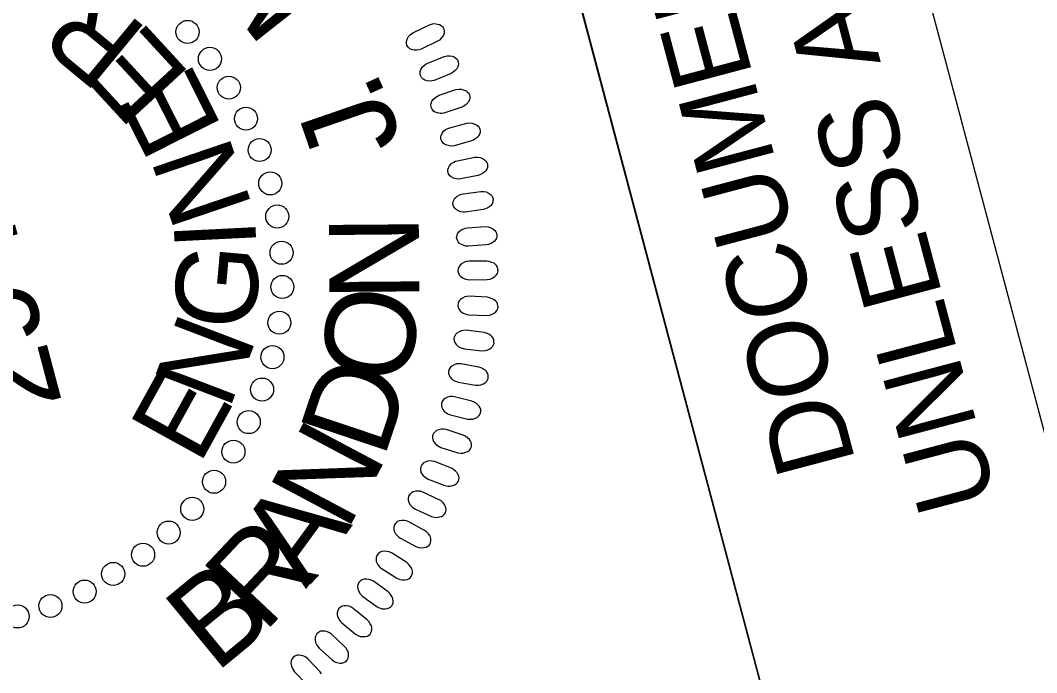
# Model space of a CAD drawing. Extents: x 473963 to 475454, y 503101 to 505009.
# Drawn here: x 474132.4 to 474202.9, y 504570.7 to 504616 of the extents above; entities that cross this region are included whole.
import ezdxf

# ---------------------------------------------------------------- set-up
doc = ezdxf.new("R2010")
doc.units = 0
for name, color, linetype in [('Old_Level_62', 7, 'Continuous'), ('Prop PHM Label Text', 7, 'Continuous'), ('Scratch_Level_4', 7, 'Continuous')]:
    doc.layers.add(name, color=color, linetype=linetype)

msp = doc.modelspace()

# ---------------------------------------------------------------- linework, layer by layer
at = {"layer": 'Old_Level_62'}
for p, q in [((474157.153, 504761.696), (474208.514, 504568.365)), ((474157.153, 504761.696), (474208.514, 504568.365)), ((474185.802, 504562.331), (474134.441, 504755.662)), ((474185.802, 504562.331), (474134.441, 504755.662))]:
    msp.add_line(p, q, dxfattribs=at)
at = {"layer": 'Prop PHM Label Text'}
msp.add_lwpolyline([(474077.089, 504533.437), (474051.4, 504630.133), (474160.141, 504659.021), (474185.802, 504562.331)], close=True, dxfattribs=at)
at = {"layer": 'Scratch_Level_4'}
for points in [[(474159.665, 504615.206), (474160.771, 504615.737), (474160.985, 504615.799), (474161.133, 504615.812), (474161.335, 504615.785), (474161.476, 504615.744), (474161.597, 504615.678), (474161.678, 504615.601), (474161.744, 504615.508), (474161.774, 504615.398), (474161.799, 504615.278), (474161.791, 504615.157), (474161.746, 504615.02), (474161.7, 504614.932), (474161.594, 504614.806), (474161.459, 504614.674), (474161.324, 504614.585), (474160.195, 504614.034), (474160.033, 504613.981), (474159.887, 504613.961), (474159.705, 504613.973), (474159.53, 504614.013), (474159.416, 504614.066), (474159.294, 504614.182), (474159.212, 504614.308), (474159.183, 504614.46), (474159.182, 504614.576), (474159.217, 504614.734), (474159.318, 504614.915), (474159.451, 504615.054), (474159.555, 504615.137)], [(474160.656, 504613.074), (474161.793, 504613.535), (474162.01, 504613.583), (474162.16, 504613.587), (474162.359, 504613.547), (474162.497, 504613.498), (474162.613, 504613.424), (474162.689, 504613.342), (474162.75, 504613.245), (474162.773, 504613.134), (474162.791, 504613.012), (474162.775, 504612.892), (474162.721, 504612.758), (474162.67, 504612.672), (474162.556, 504612.553), (474162.413, 504612.431), (474162.273, 504612.35), (474161.111, 504611.871), (474160.946, 504611.829), (474160.8, 504611.818), (474160.618, 504611.841), (474160.447, 504611.892), (474160.336, 504611.952), (474160.222, 504612.075), (474160.147, 504612.207), (474160.128, 504612.36), (474160.135, 504612.476), (474160.179, 504612.631), (474160.292, 504612.805), (474160.433, 504612.936), (474160.542, 504613.011)], [(474161.451, 504610.838), (474162.615, 504611.226), (474162.835, 504611.26), (474162.983, 504611.255), (474163.18, 504611.202), (474163.315, 504611.145), (474163.426, 504611.063), (474163.497, 504610.977), (474163.551, 504610.877), (474163.567, 504610.765), (474163.577, 504610.641), (474163.554, 504610.523), (474163.492, 504610.392), (474163.435, 504610.31), (474163.315, 504610.199), (474163.163, 504610.085), (474163.019, 504610.014), (474161.83, 504609.608), (474161.662, 504609.576), (474161.515, 504609.575), (474161.335, 504609.61), (474161.167, 504609.671), (474161.061, 504609.739), (474160.954, 504609.868), (474160.888, 504610.004), (474160.879, 504610.158), (474160.893, 504610.273), (474160.947, 504610.425), (474161.07, 504610.592), (474161.219, 504610.714), (474161.333, 504610.783)], [(474162.177, 504608.581), (474163.363, 504608.896), (474163.584, 504608.916), (474163.733, 504608.901), (474163.926, 504608.836), (474164.057, 504608.77), (474164.163, 504608.682), (474164.228, 504608.592), (474164.275, 504608.488), (474164.285, 504608.375), (474164.287, 504608.252), (474164.257, 504608.135), (474164.186, 504608.008), (474164.124, 504607.93), (474163.997, 504607.827), (474163.839, 504607.723), (474163.691, 504607.66), (474162.478, 504607.331), (474162.309, 504607.309), (474162.162, 504607.317), (474161.985, 504607.362), (474161.821, 504607.435), (474161.719, 504607.509), (474161.621, 504607.645), (474161.563, 504607.785), (474161.563, 504607.939), (474161.585, 504608.053), (474161.648, 504608.202), (474161.782, 504608.36), (474161.938, 504608.472), (474162.056, 504608.533)], [(474162.712, 504606.289), (474163.915, 504606.528), (474164.137, 504606.534), (474164.285, 504606.51), (474164.473, 504606.433), (474164.6, 504606.36), (474164.699, 504606.265), (474164.759, 504606.17), (474164.801, 504606.063), (474164.802, 504605.95), (474164.797, 504605.827), (474164.759, 504605.713), (474164.681, 504605.591), (474164.615, 504605.516), (474164.481, 504605.421), (474164.317, 504605.327), (474164.164, 504605.274), (474162.934, 504605.022), (474162.763, 504605.011), (474162.617, 504605.028), (474162.443, 504605.084), (474162.284, 504605.166), (474162.187, 504605.247), (474162.098, 504605.389), (474162.049, 504605.532), (474162.059, 504605.686), (474162.088, 504605.798), (474162.16, 504605.943), (474162.304, 504606.093), (474162.467, 504606.194), (474162.588, 504606.248)], [(474163.116, 504603.998), (474164.332, 504604.161), (474164.554, 504604.154), (474164.7, 504604.121), (474164.883, 504604.032), (474165.004, 504603.95), (474165.099, 504603.85), (474165.152, 504603.752), (474165.186, 504603.643), (474165.181, 504603.53), (474165.168, 504603.407), (474165.123, 504603.295), (474165.037, 504603.179), (474164.966, 504603.108), (474164.827, 504603.022), (474164.657, 504602.938), (474164.502, 504602.895), (474163.258, 504602.72), (474163.087, 504602.72), (474162.942, 504602.746), (474162.773, 504602.813), (474162.619, 504602.905), (474162.527, 504602.991), (474162.447, 504603.139), (474162.407, 504603.285), (474162.427, 504603.438), (474162.462, 504603.548), (474162.544, 504603.688), (474162.696, 504603.828), (474162.865, 504603.919), (474162.99, 504603.966)], [(474163.408, 504601.628), (474164.632, 504601.714), (474164.853, 504601.693), (474164.997, 504601.651), (474165.174, 504601.551), (474165.29, 504601.461), (474165.377, 504601.355), (474165.425, 504601.254), (474165.452, 504601.143), (474165.44, 504601.03), (474165.419, 504600.909), (474165.367, 504600.8), (474165.275, 504600.689), (474165.199, 504600.623), (474165.055, 504600.546), (474164.88, 504600.473), (474164.722, 504600.439), (474163.47, 504600.343), (474163.299, 504600.354), (474163.156, 504600.389), (474162.991, 504600.467), (474162.844, 504600.569), (474162.757, 504600.66), (474162.687, 504600.812), (474162.656, 504600.961), (474162.686, 504601.112), (474162.728, 504601.22), (474162.817, 504601.354), (474162.979, 504601.484), (474163.153, 504601.565), (474163.28, 504601.603)], [(474163.551, 504598.022), (474164.778, 504598.031), (474164.996, 504598.071), (474165.136, 504598.123), (474165.305, 504598.237), (474165.414, 504598.335), (474165.493, 504598.448), (474165.532, 504598.553), (474165.551, 504598.665), (474165.53, 504598.777), (474165.499, 504598.897), (474165.439, 504599.001), (474165.338, 504599.104), (474165.258, 504599.164), (474165.108, 504599.23), (474164.927, 504599.288), (474164.768, 504599.309), (474163.511, 504599.307), (474163.342, 504599.283), (474163.203, 504599.237), (474163.044, 504599.146), (474162.905, 504599.033), (474162.826, 504598.935), (474162.767, 504598.777), (474162.749, 504598.628), (474162.79, 504598.478), (474162.841, 504598.374), (474162.941, 504598.248), (474163.112, 504598.13), (474163.292, 504598.064), (474163.422, 504598.035)], [(474163.5, 504595.594), (474164.725, 504595.527), (474164.946, 504595.552), (474165.088, 504595.596), (474165.264, 504595.699), (474165.379, 504595.79), (474165.464, 504595.899), (474165.51, 504596), (474165.536, 504596.111), (474165.522, 504596.224), (474165.499, 504596.345), (474165.445, 504596.453), (474165.351, 504596.563), (474165.275, 504596.627), (474165.129, 504596.703), (474164.953, 504596.772), (474164.795, 504596.803), (474163.541, 504596.88), (474163.37, 504596.866), (474163.228, 504596.829), (474163.064, 504596.748), (474162.919, 504596.644), (474162.833, 504596.551), (474162.765, 504596.398), (474162.737, 504596.25), (474162.769, 504596.098), (474162.813, 504595.991), (474162.905, 504595.858), (474163.068, 504595.73), (474163.244, 504595.653), (474163.372, 504595.616)], [(474163.195, 504593.228), (474164.413, 504593.084), (474164.636, 504593.095), (474164.781, 504593.13), (474164.962, 504593.222), (474165.083, 504593.305), (474165.175, 504593.408), (474165.227, 504593.507), (474165.26, 504593.616), (474165.253, 504593.729), (474165.237, 504593.852), (474165.191, 504593.963), (474165.103, 504594.078), (474165.031, 504594.147), (474164.891, 504594.231), (474164.72, 504594.312), (474164.564, 504594.353), (474163.316, 504594.508), (474163.146, 504594.506), (474163.002, 504594.477), (474162.833, 504594.407), (474162.681, 504594.312), (474162.59, 504594.225), (474162.512, 504594.076), (474162.475, 504593.929), (474162.498, 504593.777), (474162.535, 504593.667), (474162.618, 504593.529), (474162.773, 504593.391), (474162.944, 504593.303), (474163.068, 504593.258)], [(474162.767, 504590.913), (474163.974, 504590.693), (474164.196, 504590.69), (474164.343, 504590.716), (474164.53, 504590.796), (474164.656, 504590.872), (474164.754, 504590.968), (474164.812, 504591.063), (474164.852, 504591.171), (474164.852, 504591.284), (474164.844, 504591.407), (474164.804, 504591.521), (474164.725, 504591.642), (474164.657, 504591.716), (474164.522, 504591.808), (474164.356, 504591.9), (474164.203, 504591.951), (474162.969, 504592.183), (474162.797, 504592.191), (474162.652, 504592.172), (474162.479, 504592.113), (474162.321, 504592.028), (474162.226, 504591.946), (474162.139, 504591.802), (474162.092, 504591.658), (474162.104, 504591.505), (474162.135, 504591.392), (474162.21, 504591.25), (474162.355, 504591.102), (474162.52, 504591.004), (474162.642, 504590.951)], [(474162.226, 504588.638), (474163.417, 504588.343), (474163.639, 504588.326), (474163.787, 504588.343), (474163.979, 504588.411), (474164.109, 504588.479), (474164.213, 504588.569), (474164.277, 504588.66), (474164.323, 504588.765), (474164.331, 504588.878), (474164.331, 504589.001), (474164.298, 504589.117), (474164.226, 504589.243), (474164.164, 504589.32), (474164.034, 504589.422), (474163.874, 504589.523), (474163.725, 504589.583), (474162.507, 504589.893), (474162.338, 504589.912), (474162.191, 504589.902), (474162.015, 504589.854), (474161.852, 504589.779), (474161.751, 504589.703), (474161.655, 504589.565), (474161.6, 504589.425), (474161.603, 504589.271), (474161.626, 504589.157), (474161.692, 504589.009), (474161.828, 504588.853), (474161.986, 504588.744), (474162.104, 504588.684)], [(474161.57, 504586.376), (474162.74, 504586.006), (474162.96, 504585.976), (474163.109, 504585.983), (474163.305, 504586.039), (474163.438, 504586.099), (474163.548, 504586.182), (474163.618, 504586.269), (474163.67, 504586.37), (474163.685, 504586.483), (474163.693, 504586.606), (474163.667, 504586.724), (474163.604, 504586.854), (474163.546, 504586.935), (474163.424, 504587.044), (474163.271, 504587.155), (474163.125, 504587.225), (474161.929, 504587.611), (474161.76, 504587.64), (474161.614, 504587.639), (474161.435, 504587.602), (474161.268, 504587.538), (474161.162, 504587.468), (474161.057, 504587.337), (474160.994, 504587.2), (474160.987, 504587.046), (474161.003, 504586.931), (474161.059, 504586.78), (474161.185, 504586.615), (474161.337, 504586.496), (474161.451, 504586.429)], [(474160.692, 504584.175), (474161.837, 504583.733), (474162.055, 504583.689), (474162.204, 504583.687), (474162.403, 504583.73), (474162.54, 504583.782), (474162.655, 504583.857), (474162.73, 504583.94), (474162.789, 504584.038), (474162.811, 504584.149), (474162.825, 504584.272), (474162.808, 504584.391), (474162.752, 504584.525), (474162.7, 504584.609), (474162.584, 504584.726), (474162.438, 504584.846), (474162.298, 504584.925), (474161.129, 504585.385), (474160.962, 504585.425), (474160.816, 504585.433), (474160.635, 504585.408), (474160.464, 504585.354), (474160.355, 504585.292), (474160.242, 504585.167), (474160.169, 504585.034), (474160.153, 504584.88), (474160.162, 504584.765), (474160.208, 504584.611), (474160.324, 504584.438), (474160.467, 504584.31), (474160.577, 504584.236)], [(474159.796, 504582.094), (474160.91, 504581.58), (474161.125, 504581.523), (474161.274, 504581.512), (474161.475, 504581.543), (474161.615, 504581.586), (474161.735, 504581.653), (474161.815, 504581.732), (474161.88, 504581.826), (474161.908, 504581.935), (474161.931, 504582.056), (474161.921, 504582.176), (474161.873, 504582.314), (474161.827, 504582.401), (474161.719, 504582.525), (474161.581, 504582.654), (474161.445, 504582.742), (474160.307, 504583.274), (474160.144, 504583.325), (474159.998, 504583.342), (474159.816, 504583.328), (474159.642, 504583.285), (474159.528, 504583.229), (474159.409, 504583.112), (474159.328, 504582.984), (474159.302, 504582.832), (474159.304, 504582.716), (474159.341, 504582.559), (474159.445, 504582.38), (474159.58, 504582.242), (474159.685, 504582.162)], [(474158.751, 504580.068), (474159.831, 504579.486), (474160.042, 504579.414), (474160.189, 504579.394), (474160.392, 504579.412), (474160.535, 504579.446), (474160.658, 504579.506), (474160.742, 504579.579), (474160.813, 504579.669), (474160.849, 504579.777), (474160.879, 504579.897), (474160.877, 504580.017), (474160.838, 504580.156), (474160.797, 504580.247), (474160.697, 504580.378), (474160.567, 504580.515), (474160.438, 504580.611), (474159.335, 504581.214), (474159.175, 504581.274), (474159.031, 504581.301), (474158.848, 504581.298), (474158.672, 504581.266), (474158.556, 504581.218), (474158.428, 504581.109), (474158.339, 504580.986), (474158.304, 504580.835), (474158.299, 504580.72), (474158.325, 504580.561), (474158.418, 504580.375), (474158.544, 504580.23), (474158.644, 504580.142)], [(474157.478, 504577.934), (474158.519, 504577.285), (474158.724, 504577.201), (474158.871, 504577.171), (474159.074, 504577.176), (474159.219, 504577.201), (474159.346, 504577.254), (474159.435, 504577.322), (474159.511, 504577.406), (474159.553, 504577.512), (474159.591, 504577.63), (474159.596, 504577.75), (474159.566, 504577.892), (474159.531, 504577.984), (474159.439, 504578.121), (474159.319, 504578.267), (474159.195, 504578.37), (474158.133, 504579.041), (474157.977, 504579.112), (474157.835, 504579.147), (474157.652, 504579.156), (474157.474, 504579.135), (474157.355, 504579.094), (474157.221, 504578.993), (474157.125, 504578.876), (474157.08, 504578.728), (474157.067, 504578.613), (474157.084, 504578.452), (474157.165, 504578.262), (474157.282, 504578.109), (474157.376, 504578.016)], [(474156.155, 504576.02), (474157.153, 504575.307), (474157.353, 504575.21), (474157.497, 504575.171), (474157.7, 504575.164), (474157.846, 504575.179), (474157.976, 504575.224), (474158.069, 504575.286), (474158.15, 504575.366), (474158.199, 504575.468), (474158.244, 504575.583), (474158.257, 504575.703), (474158.236, 504575.846), (474158.206, 504575.941), (474158.123, 504576.083), (474158.012, 504576.236), (474157.896, 504576.347), (474156.877, 504577.084), (474156.727, 504577.164), (474156.586, 504577.208), (474156.405, 504577.228), (474156.226, 504577.218), (474156.105, 504577.186), (474155.964, 504577.093), (474155.861, 504576.982), (474155.807, 504576.838), (474155.787, 504576.723), (474155.794, 504576.562), (474155.862, 504576.366), (474155.969, 504576.207), (474156.058, 504576.107)], [(474154.696, 504574.181), (474155.648, 504573.406), (474155.842, 504573.297), (474155.983, 504573.248), (474156.185, 504573.229), (474156.332, 504573.235), (474156.464, 504573.272), (474156.561, 504573.328), (474156.648, 504573.402), (474156.703, 504573.501), (474156.755, 504573.613), (474156.775, 504573.732), (474156.763, 504573.876), (474156.739, 504573.973), (474156.666, 504574.12), (474156.565, 504574.279), (474156.455, 504574.398), (474155.485, 504575.196), (474155.339, 504575.286), (474155.203, 504575.339), (474155.022, 504575.371), (474154.844, 504575.372), (474154.72, 504575.347), (474154.574, 504575.263), (474154.465, 504575.159), (474154.402, 504575.018), (474154.374, 504574.906), (474154.371, 504574.744), (474154.427, 504574.545), (474154.524, 504574.379), (474154.605, 504574.274)], [(474153.115, 504572.44), (474154.017, 504571.607), (474154.203, 504571.485), (474154.341, 504571.429), (474154.542, 504571.397), (474154.688, 504571.393), (474154.823, 504571.422), (474154.923, 504571.472), (474155.014, 504571.54), (474155.075, 504571.637), (474155.134, 504571.744), (474155.162, 504571.862), (474155.159, 504572.006), (474155.141, 504572.104), (474155.077, 504572.256), (474154.986, 504572.421), (474154.884, 504572.546), (474153.966, 504573.404), (474153.827, 504573.503), (474153.693, 504573.564), (474153.515, 504573.607), (474153.337, 504573.62), (474153.212, 504573.602), (474153.061, 504573.527), (474152.945, 504573.431), (474152.873, 504573.295), (474152.839, 504573.184), (474152.826, 504573.022), (474152.869, 504572.82), (474152.956, 504572.648), (474153.031, 504572.539)]]:
    msp.add_lwpolyline(points, close=True, dxfattribs=at)
msp.add_lwpolyline([(474153.273, 504570.653), (474153.179, 504570.785), (474152.317, 504571.699), (474152.183, 504571.806), (474152.054, 504571.876), (474151.879, 504571.929), (474151.702, 504571.953), (474151.576, 504571.944), (474151.422, 504571.878), (474151.3, 504571.789), (474151.219, 504571.657), (474151.178, 504571.549), (474151.155, 504571.39), (474151.186, 504571.184), (474151.261, 504571.008), (474151.328, 504570.894), (474151.407, 504570.79), (474152.254, 504569.902)], dxfattribs=at)
for centre in [(474143.974, 504615.236), (474145.529, 504613.365), (474146.843, 504611.366), (474148.033, 504609.21), (474148.982, 504607.032), (474149.72, 504604.715), (474150.207, 504602.414), (474150.504, 504599.898), (474150.557, 504597.523), (474150.35, 504595.038), (474149.872, 504592.645), (474149.151, 504590.394), (474148.226, 504588.131), (474147.164, 504586.078), (474145.821, 504583.992), (474144.302, 504582.106), (474142.666, 504580.461), (474140.89, 504578.919), (474138.812, 504577.585), (474136.83, 504576.359), (474134.457, 504575.359), (474132.178, 504574.631)]:
    msp.add_circle(centre, 0.801, dxfattribs=at)

# ---------------------------------------------------------------- texts
at = {"layer": 'Old_Level_62'}
for s, p in [('UNLESS ALL SIGNATURES COMPLETED', (474200.198, 504582.71)), ('UNLESS ALL SIGNATURES COMPLETED', (474200.198, 504582.71)), ('DOCUMENT NOT CONSIDERED FINAL', (474190.391, 504585.352)), ('DOCUMENT NOT CONSIDERED FINAL', (474190.391, 504585.352))]:
    msp.add_text(s, height=5.5, rotation=104.87785, dxfattribs=at).set_placement(p)
at = {"layer": 'Scratch_Level_4'}
for s, height, rotation, p in [('M', 6.236, 128.21817, (474154.067, 504617.915)), ('R', 5.669, 140.54141, (474141.333, 504615.321)), ('E', 5.669, 132.60162, (474144.297, 504612.196)), ('E', 5.669, 116.72202, (474146.427, 504608.551)), ('.', 6.236, 114.51556, (474157.874, 504610.674)), ('29470', 6.2363, 104.85921, (474135.297, 504589.422)), ('J', 6.236, 109.02356, (474158.897, 504607.551)), ('N', 5.669, 108.78222, (474148.515, 504603.054)), ('I', 5.669, 92.90263, (474148.765, 504600.272)), ('N', 6.236, 90.42836, (474160.073, 504596.533)), ('G', 5.669, 84.96283, (474148.577, 504594.398)), ('O', 6.236, 80.32851, (474159.206, 504590.558)), ('N', 5.669, 69.08324, (474146.839, 504588.873)), ('D', 6.236, 71.46028, (474157.591, 504585.508)), ('E', 5.669, 61.14344, (474144.788, 504585.084)), ('N', 6.236, 61.9706, (474155.023, 504580.449)), ('A', 6.236, 53.85942, (474152.191, 504576.511)), ('R', 6.236, 46.74258, (474149.27, 504573.414)), ('B', 6.236, 39.46755, (474145.911, 504570.648))]:
    msp.add_text(s, height=height, rotation=rotation, dxfattribs=at).set_placement(p)

doc.saveas('drawing.dxf')
